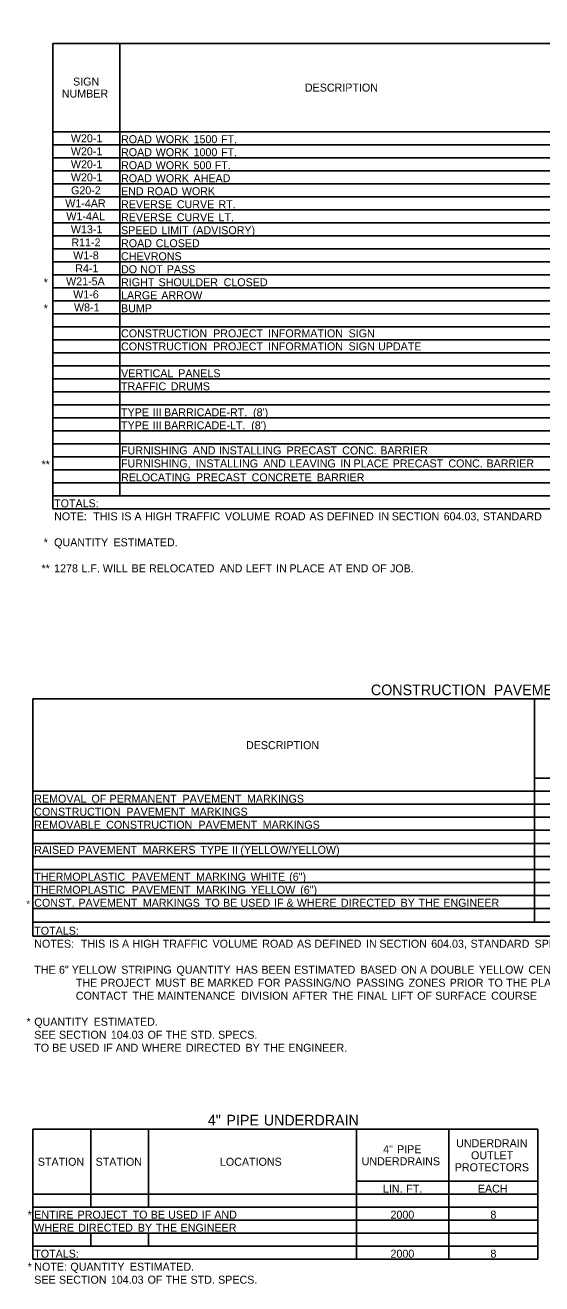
# Model space of a CAD drawing. Extents: x 977434 to 989596, y 1525697 to 1528336.
# Drawn here: x 979085 to 979473, y 1527367 to 1528310 of the extents above; entities that cross this region are included whole.
import ezdxf

# ---------------------------------------------------------------- set-up
doc = ezdxf.new("R2010")
doc.units = 0
doc.layers.add('Default', color=7, linetype='Continuous')
doc.layers.add('R_Border Prem', color=7, linetype='Continuous')

msp = doc.modelspace()

# ---------------------------------------------------------------- linework, layer by layer
at = {"layer": 'Default'}
for p, q in [((979105.72, 1528296.72), (980364.94, 1528296.72)), ((979105.72, 1527947.67), (979105.72, 1528296.72)), ((979105.72, 1527947.67), (979105.72, 1528296.72)), ((979155.94, 1527957.42), (979155.94, 1528296.72)), ((979105.72, 1528230.42), (980364.94, 1528230.42)), ((979155.94, 1527996.42), (979155.94, 1528230.42)), ((979105.72, 1528220.67), (980364.94, 1528220.67)), ((979105.72, 1528210.92), (980364.94, 1528210.92)), ((979105.72, 1528201.17), (980364.94, 1528201.17)), ((979105.72, 1528191.42), (980364.94, 1528191.42)), ((979105.72, 1528181.67), (980364.94, 1528181.67)), ((979105.72, 1528171.92), (980364.94, 1528171.92)), ((979105.72, 1528162.17), (980364.94, 1528162.17)), ((979105.72, 1528152.42), (980364.94, 1528152.42)), ((979105.72, 1528142.67), (980364.94, 1528142.67)), ((979105.72, 1528132.92), (980364.94, 1528132.92)), ((979105.72, 1528123.17), (980364.94, 1528123.17)), ((979105.72, 1528113.42), (980364.94, 1528113.42)), ((979105.72, 1528103.67), (980364.94, 1528103.67)), ((979105.72, 1528093.92), (980364.94, 1528093.92)), ((979105.72, 1528084.17), (980364.94, 1528084.17)), ((979105.72, 1528074.42), (980364.94, 1528074.42)), ((979105.72, 1528064.67), (980364.94, 1528064.67)), ((979105.72, 1528054.92), (980364.94, 1528054.92)), ((979105.72, 1528045.17), (980364.94, 1528045.17)), ((979105.72, 1528035.42), (980364.94, 1528035.42)), ((979105.72, 1528025.67), (980364.94, 1528025.67)), ((979105.72, 1528015.92), (980364.94, 1528015.92)), ((979105.72, 1528006.17), (980364.94, 1528006.17)), ((979105.72, 1527996.42), (980364.94, 1527996.42)), ((979105.72, 1527986.67), (979155.94, 1527986.67)), ((979105.72, 1527986.67), (980364.94, 1527986.67)), ((979105.72, 1527976.92), (979155.94, 1527976.92)), ((979105.72, 1527976.92), (980364.94, 1527976.92)), ((979155.94, 1527957.42), (979155.94, 1527976.92)), ((979105.72, 1527967.17), (980364.94, 1527967.17)), ((979105.72, 1527957.42), (980364.94, 1527957.42)), ((979105.72, 1527947.67), (980364.94, 1527947.67)), ((979090.8, 1527805.18), (980044.35, 1527805.18)), ((979090.8, 1527627.25), (979090.8, 1527805.18)), ((979090.8, 1527627.25), (979090.8, 1527805.18)), ((979467.15, 1527637.97), (979467.15, 1527805.18)), ((979467.15, 1527745.71), (980044.35, 1527745.71)), ((979090.8, 1527735.96), (980044.35, 1527735.96)), ((979467.15, 1527637.97), (979467.15, 1527735.96)), ((979090.8, 1527726.21), (980044.35, 1527726.21)), ((979090.8, 1527716.46), (980044.35, 1527716.46)), ((979090.8, 1527706.71), (980044.35, 1527706.71)), ((979090.8, 1527696.96), (980044.35, 1527696.96)), ((979090.8, 1527687.21), (980044.35, 1527687.21)), ((979090.8, 1527677.46), (980044.35, 1527677.46)), ((979090.8, 1527667.71), (980044.35, 1527667.71)), ((979090.8, 1527657.96), (980044.35, 1527657.96)), ((979090.8, 1527648.21), (980044.35, 1527648.21)), ((979090.8, 1527637.97), (980044.35, 1527637.97)), ((979090.8, 1527627.25), (980044.35, 1527627.25)), ((979090.8, 1527482.59), (979469.59, 1527482.59)), ((979090.8, 1527385.09), (979090.8, 1527482.59)), ((979090.8, 1527385.09), (979090.8, 1527482.59)), ((979134.19, 1527424.09), (979134.19, 1527482.59)), ((979177.58, 1527424.09), (979177.58, 1527482.59)), ((979333.58, 1527385.09), (979333.58, 1527482.59)), ((979402.8, 1527385.09), (979402.8, 1527482.59)), ((979469.59, 1527385.09), (979469.59, 1527482.59)), ((979469.59, 1527385.09), (979469.59, 1527482.59)), ((979333.58, 1527443.59), (979469.59, 1527443.59)), ((979090.8, 1527433.84), (979402.8, 1527433.84)), ((979090.8, 1527433.84), (979333.58, 1527433.84)), ((979333.58, 1527385.09), (979333.58, 1527433.84)), ((979402.8, 1527433.84), (979469.59, 1527433.84)), ((979402.8, 1527433.84), (979469.59, 1527433.84)), ((979090.8, 1527424.09), (979469.59, 1527424.09)), ((979090.8, 1527414.34), (979469.59, 1527414.34)), ((979090.8, 1527404.59), (979469.59, 1527404.59)), ((979134.19, 1527394.84), (979134.19, 1527404.59)), ((979177.58, 1527394.84), (979177.58, 1527404.59)), ((979090.8, 1527394.84), (979469.59, 1527394.84)), ((979090.8, 1527385.09), (979469.59, 1527385.09))]:
    msp.add_line(p, q, dxfattribs=at)
at = {"layer": 'R_Border Prem'}
for p, q in [((979095, 1528310.37), (979095, 1528310.37)), ((979084.95, 1527818.83), (979084.95, 1527818.83)), ((979084.95, 1527496.24), (979084.95, 1527496.24))]:
    msp.add_line(p, q, dxfattribs=at)

# ---------------------------------------------------------------- texts
at = {"layer": 'Default'}
for s, height, p in [('SIGN', 6, (979120.92, 1528265.07)), ('NUMBER', 6, (979112.45, 1528256.07)), ('DESCRIPTION', 6, (979294.84, 1528260.57)), ('W20-1', 6, (979119.26, 1528222.54)), ('ROAD', 6, (979156.91, 1528221.87)), (' WORK', 6, (979180.69, 1528221.87)), (' 1500', 6, (979209.08, 1528221.87)), (' FT.', 6, (979229.64, 1528221.87)), ('W20-1', 6, (979119.26, 1528212.79)), ('ROAD', 6, (979156.91, 1528212.12)), (' WORK', 6, (979180.69, 1528212.12)), (' 1000', 6, (979209.08, 1528212.12)), (' FT.', 6, (979229.64, 1528212.12)), ('W20-1', 6, (979119.26, 1528203.04)), ('ROAD', 6, (979156.91, 1528202.37)), (' WORK', 6, (979180.69, 1528202.37)), (' 500', 6, (979209.08, 1528202.37)), (' FT.', 6, (979224.98, 1528202.37)), ('W20-1', 6, (979119.26, 1528193.29)), ('ROAD', 6, (979156.91, 1528192.62)), (' WORK', 6, (979180.69, 1528192.62)), (' AHEAD', 6, (979209.08, 1528192.62)), ('G20-2', 6, (979119.41, 1528183.54)), ('END', 6, (979156.91, 1528182.87)), (' ROAD', 6, (979174.16, 1528182.87)), (' WORK', 6, (979200.27, 1528182.87)), ('W1-4AR', 6, (979115.05, 1528173.79)), ('REVERSE', 6, (979156.91, 1528173.12)), (' CURVE', 6, (979196.54, 1528173.12)), (' RT.', 6, (979227.77, 1528173.12)), ('W1-4AL', 6, (979115.84, 1528164.04)), ('REVERSE', 6, (979156.91, 1528163.37)), (' CURVE', 6, (979196.54, 1528163.37)), (' LT.', 6, (979227.77, 1528163.37)), ('W13-1', 6, (979119.26, 1528154.29)), ('SPEED', 6, (979156.91, 1528153.62)), (' LIMIT', 6, (979184.89, 1528153.62)), (' (ADVISORY)', 6, (979208.47, 1528153.62)), ('R11-2', 6, (979119.64, 1528144.54)), ('ROAD', 6, (979156.91, 1528143.87)), (' CLOSED', 6, (979180.69, 1528143.87)), ('W1-8', 6, (979121, 1528134.79)), ('CHEVRONS', 6, (979156.91, 1528134.12)), ('R4-1', 6, (979122.52, 1528125.04)), ('DO', 6, (979156.91, 1528124.37)), (' NOT', 6, (979169.11, 1528124.37)), (' PASS', 6, (979188.97, 1528124.37)), ('*', 6, (979098.88, 1528114.62)), ('W21-5A', 6, (979115.68, 1528115.29)), ('RIGHT', 6, (979156.91, 1528114.62)), (' SHOULDER', 6, (979182.82, 1528114.62)), (' CLOSED', 6, (979231.62, 1528114.62)), ('W1-6', 6, (979121.01, 1528105.54)), ('LARGE', 6, (979156.91, 1528104.87)), (' ARROW', 6, (979184.88, 1528104.87)), ('*', 6, (979098.88, 1528095.12)), ('W8-1', 6, (979121.59, 1528095.79)), ('BUMP', 6, (979156.91, 1528095.12)), ('CONSTRUCTION', 6, (979156.91, 1528076.29)), (' PROJECT', 6, (979223.76, 1528076.29)), (' INFORMATION', 6, (979265.05, 1528076.29)), (' SIGN', 6, (979325.38, 1528076.29)), ('CONSTRUCTION', 6, (979156.91, 1528066.54)), (' PROJECT', 6, (979223.76, 1528066.54)), (' INFORMATION', 6, (979265.05, 1528066.54)), (' SIGN', 6, (979325.38, 1528066.54)), (' UPDATE', 6, (979347.52, 1528066.54)), ('VERTICAL', 6, (979156.91, 1528046.37)), (' PANELS', 6, (979197.61, 1528046.37)), ('TRAFFIC', 6, (979156.91, 1528036.62)), (' DRUMS', 6, (979191.97, 1528036.62)), ('TYPE', 6, (979156.91, 1528017.12)), (' III', 6, (979178.36, 1528017.12)), (' BARRICADE-RT.', 6, (979186.92, 1528017.12)), (" (8')", 6, (979253.73, 1528017.12)), ('TYPE', 6, (979156.91, 1528007.37)), (' III', 6, (979178.36, 1528007.37)), (' BARRICADE-LT.', 6, (979186.92, 1528007.37)), (" (8')", 6, (979252.34, 1528007.37)), ('FURNISHING', 6, (979156.91, 1527988.54)), (' AND', 6, (979208.55, 1527988.54)), (' INSTALLING', 6, (979228.13, 1527988.54)), (' PRECAST', 6, (979278.85, 1527988.54)), (' CONC.', 6, (979320.61, 1527988.54)), (' BARRIER', 6, (979349.22, 1527988.54)), ('**', 6, (979097.25, 1527978.12)), ('FURNISHING,', 6, (979156.91, 1527978.79)), (' INSTALLING', 6, (979210.66, 1527978.79)), (' AND', 6, (979261.38, 1527978.79)), (' LEAVING', 6, (979280.96, 1527978.79)), (' IN', 6, (979319.1, 1527978.79)), (' PLACE', 6, (979329.13, 1527978.79)), (' PRECAST', 6, (979358.5, 1527978.79)), (' CONC.', 6, (979400.26, 1527978.79)), (' BARRIER', 6, (979428.87, 1527978.79)), ('RELOCATING', 6, (979156.91, 1527968.37)), (' PRECAST', 6, (979210.89, 1527968.37)), (' CONCRETE', 6, (979252.65, 1527968.37)), (' BARRIER', 6, (979301.58, 1527968.37)), ('TOTALS:', 6, (979106.7, 1527948.87)), ('NOTE:', 6, (979106.7, 1527939.12)), ('  THIS', 6, (979131.58, 1527939.12)), (' IS', 6, (979154.9, 1527939.12)), (' A', 6, (979164.71, 1527939.12)), (' HIGH', 6, (979172.64, 1527939.12)), (' TRAFFIC', 6, (979195.25, 1527939.12)), (' VOLUME', 6, (979232.64, 1527939.12)), (' ROAD', 6, (979269.93, 1527939.12)), (' AS', 6, (979296.03, 1527939.12)), (' DEFINED', 6, (979309.11, 1527939.12)), (' IN', 6, (979347.79, 1527939.12)), (' SECTION', 6, (979357.81, 1527939.12)), (' 604.03,', 6, (979396.72, 1527939.12)), (' STANDARD', 6, (979426.26, 1527939.12)), ('*', 6, (979098.88, 1527919.62)), ('QUANTITY', 6, (979106.7, 1527919.62)), (' ESTIMATED.', 6, (979149.02, 1527919.62)), ('**', 6, (979097.25, 1527900.12)), ('1278', 6, (979106.7, 1527900.12)), (' L.F.', 6, (979124.97, 1527900.12)), (' WILL', 6, (979141, 1527900.12)), (' BE', 6, (979162.59, 1527900.12)), (' RELOCATED', 6, (979175.66, 1527900.12)), (' AND', 6, (979228.78, 1527900.12)), (' LEFT', 6, (979248.37, 1527900.12)), (' IN', 6, (979271.02, 1527900.12)), (' PLACE', 6, (979281.05, 1527900.12)), (' AT', 6, (979310.42, 1527900.12)), (' END', 6, (979323.29, 1527900.12)), (' OF', 6, (979342.87, 1527900.12)), (' JOB.', 6, (979356.46, 1527900.12)), ('CONSTRUCTION', 8, (979344.38, 1527808.01)), (' PAVEMENT', 8, (979433.53, 1527808.01)), ('DESCRIPTION', 6, (979250.67, 1527767.57)), ('REMOVAL', 6, (979091.78, 1527727.41)), (' OF', 6, (979132.48, 1527727.41)), (' PERMANENT', 6, (979146.07, 1527727.41)), (' PAVEMENT', 6, (979200.87, 1527727.41)), (' MARKINGS', 6, (979249.15, 1527727.41)), ('CONSTRUCTION', 6, (979091.78, 1527717.66)), (' PAVEMENT', 6, (979158.63, 1527717.66)), (' MARKINGS', 6, (979206.91, 1527717.66)), ('REMOVABLE', 6, (979091.78, 1527707.91)), (' CONSTRUCTION', 6, (979143.52, 1527707.91)), (' PAVEMENT', 6, (979212.69, 1527707.91)), (' MARKINGS', 6, (979260.98, 1527707.91)), ('RAISED', 6, (979091.78, 1527689.08)), (' PAVEMENT', 6, (979122.55, 1527689.08)), (' MARKERS', 6, (979170.83, 1527689.08)), (' TYPE', 6, (979214.18, 1527689.08)), (' II', 6, (979237.97, 1527689.08)), (' (YELLOW/YELLOW)', 6, (979244.2, 1527689.08)), ('THERMOPLASTIC', 6, (979091.78, 1527668.91)), (' MARKING', 6, (979211, 1527668.91)), (' (6")', 6, (979280.82, 1527668.91)), (' PAVEMENT', 6, (979162.72, 1527668.91)), (' WHITE', 6, (979251.93, 1527668.91)), ('THERMOPLASTIC', 6, (979091.78, 1527659.16)), (' PAVEMENT', 6, (979162.72, 1527659.16)), (' MARKING', 6, (979211, 1527659.16)), (' YELLOW', 6, (979251.93, 1527659.16)), (' (6")', 6, (979289.1, 1527659.16)), ('*', 5, (979085.93, 1527649.21)), ('CONST.', 6, (979091.78, 1527649.41)), (' PAVEMENT', 6, (979122.72, 1527649.41)), (' MARKINGS', 6, (979171.01, 1527649.41)), (' TO', 6, (979217.61, 1527649.41)), (' BE', 6, (979231.21, 1527649.41)), (' USED', 6, (979244.28, 1527649.41)), (' IF', 6, (979269.45, 1527649.41)), (' &', 6, (979278.84, 1527649.41)), (' WHERE', 6, (979286.57, 1527649.41)), (' DIRECTED', 6, (979319.66, 1527649.41)), (' BY', 6, (979364.4, 1527649.41)), (' THE', 6, (979377.84, 1527649.41)), (' ENGINEER', 6, (979396.49, 1527649.41)), ('TOTALS:', 6, (979091.78, 1527628.45)), ('NOTES:', 6, (979091.78, 1527618.7)), ('  THIS', 6, (979122.26, 1527618.7)), (' IS', 6, (979145.57, 1527618.7)), (' A', 6, (979155.38, 1527618.7)), (' HIGH', 6, (979163.32, 1527618.7)), (' TRAFFIC', 6, (979185.93, 1527618.7)), (' VOLUME', 6, (979223.32, 1527618.7)), (' ROAD', 6, (979260.6, 1527618.7)), (' AS', 6, (979286.71, 1527618.7)), (' DEFINED', 6, (979299.78, 1527618.7)), (' IN', 6, (979338.46, 1527618.7)), (' SECTION', 6, (979348.49, 1527618.7)), (' 604.03,', 6, (979387.39, 1527618.7)), (' STANDARD', 6, (979416.93, 1527618.7)), (' SPECIFICATIONS', 6, (979464.93, 1527618.7)), ('THE', 6, (979091.78, 1527599.2)), (' 6"', 6, (979108.1, 1527599.2)), (' YELLOW', 6, (979117.67, 1527599.2)), (' STRIPING', 6, (979154.84, 1527599.2)), (' QUANTITY', 6, (979196.24, 1527599.2)), (' HAS', 6, (979240.89, 1527599.2)), (' BEEN', 6, (979260.02, 1527599.2)), (' ESTIMATED', 6, (979284.5, 1527599.2)), (' BASED', 6, (979334.36, 1527599.2)), (' ON', 6, (979364.67, 1527599.2)), (' A', 6, (979378.88, 1527599.2)), (' DOUBLE', 6, (979386.82, 1527599.2)), (' YELLOW', 6, (979423.17, 1527599.2)), (' CENTERLINE', 6, (979460.34, 1527599.2)), ('THE', 6, (979122.98, 1527589.45)), (' PROJECT', 6, (979139.3, 1527589.45)), (' MUST', 6, (979180.59, 1527589.45)), (' BE', 6, (979206.5, 1527589.45)), (' MARKED', 6, (979219.57, 1527589.45)), (' FOR', 6, (979257.32, 1527589.45)), (' PASSING/NO', 6, (979277.23, 1527589.45)), (' PASSING', 6, (979331.37, 1527589.45)), (' ZONES', 6, (979370.44, 1527589.45)), (' PRIOR', 6, (979401.22, 1527589.45)), (' TO', 6, (979429.98, 1527589.45)), (' THE', 6, (979443.58, 1527589.45)), (' PLACEMENT', 6, (979462.23, 1527589.45)), ('CONTACT', 6, (979122.98, 1527579.7)), (' THE', 6, (979163.33, 1527579.7)), (' MAINTENANCE', 6, (979181.98, 1527579.7)), (' DIVISION', 6, (979244.89, 1527579.7)), (' AFTER', 6, (979283.33, 1527579.7)), (' THE', 6, (979313.03, 1527579.7)), (' FINAL', 6, (979331.68, 1527579.7)), (' LIFT', 6, (979357.46, 1527579.7)), (' OF', 6, (979376.85, 1527579.7)), (' SURFACE', 6, (979390.44, 1527579.7)), (' COURSE', 6, (979432.39, 1527579.7)), ('*', 6, (979085.93, 1527560.2)), ('QUANTITY', 6, (979091.78, 1527560.2)), (' ESTIMATED.', 6, (979134.1, 1527560.2)), ('SEE', 6, (979091.78, 1527550.45)), (' SECTION', 6, (979108.11, 1527550.45)), (' 104.03', 6, (979147.02, 1527550.45)), (' OF', 6, (979174.59, 1527550.45)), (' THE', 6, (979188.18, 1527550.45)), (' STD.', 6, (979206.83, 1527550.45)), (' SPECS.', 6, (979227.52, 1527550.45)), ('TO', 6, (979091.78, 1527540.7)), (' BE', 6, (979103.05, 1527540.7)), (' USED', 6, (979116.11, 1527540.7)), (' IF', 6, (979141.29, 1527540.7)), (' AND', 6, (979150.68, 1527540.7)), (' WHERE', 6, (979170.26, 1527540.7)), (' DIRECTED', 6, (979203.35, 1527540.7)), (' BY', 6, (979248.09, 1527540.7)), (' THE', 6, (979261.54, 1527540.7)), (' ENGINEER.', 6, (979280.18, 1527540.7)), ('4"', 8, (979222.03, 1527485.42)), (' PIPE', 8, (979232.99, 1527485.42)), (' UNDERDRAIN', 8, (979261.01, 1527485.42)), ('4"', 6, (979353.57, 1527464.59)), (' PIPE', 6, (979361.79, 1527464.59)), ('UNDERDRAIN', 6, (979408.35, 1527469.09)), ('STATION', 6, (979094.44, 1527455.22)), ('STATION', 6, (979137.82, 1527455.22)), ('LOCATIONS', 6, (979231.1, 1527455.22)), ('UNDERDRAINS', 6, (979337.42, 1527455.59)), ('OUTLET', 6, (979419.52, 1527460.09)), ('PROTECTORS', 6, (979407.29, 1527451.09)), ('LIN.', 6, (979353.4, 1527435.04)), (' FT.', 6, (979368.66, 1527435.04)), ('EACH', 6, (979424.64, 1527435.04)), ('*', 6, (979086.86, 1527415.54)), ('ENTIRE', 6, (979091.78, 1527415.54)), (' PROJECT', 6, (979122.08, 1527415.54)), (' TO', 6, (979163.37, 1527415.54)), (' BE', 6, (979176.96, 1527415.54)), (' USED', 6, (979190.03, 1527415.54)), (' IF', 6, (979215.2, 1527415.54)), (' AND', 6, (979224.6, 1527415.54)), ('2000', 6, (979359.07, 1527415.54)), ('8', 6, (979434.05, 1527415.54)), ('WHERE', 6, (979091.78, 1527405.79)), (' DIRECTED', 6, (979122.54, 1527405.79)), (' BY', 6, (979167.27, 1527405.79)), (' THE', 6, (979180.72, 1527405.79)), (' ENGINEER', 6, (979199.37, 1527405.79)), ('TOTALS:', 6, (979091.78, 1527386.29)), ('2000', 6, (979359.08, 1527386.29)), ('8', 6, (979434.06, 1527386.29)), ('*', 6, (979086.86, 1527376.54)), ('NOTE:', 6, (979091.78, 1527376.54)), (' QUANTITY', 6, (979116.67, 1527376.54)), (' ESTIMATED.', 6, (979161.32, 1527376.54)), ('SEE', 6, (979091.78, 1527366.79)), (' SECTION', 6, (979108.11, 1527366.79)), (' 104.03', 6, (979147.02, 1527366.79)), (' OF', 6, (979174.59, 1527366.79)), (' THE', 6, (979188.18, 1527366.79)), (' STD.', 6, (979206.83, 1527366.79)), (' SPECS.', 6, (979227.52, 1527366.79))]:
    msp.add_text(s, height=height, dxfattribs=at).set_placement(p)

doc.saveas('drawing.dxf')
